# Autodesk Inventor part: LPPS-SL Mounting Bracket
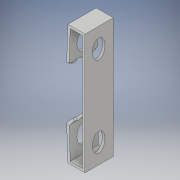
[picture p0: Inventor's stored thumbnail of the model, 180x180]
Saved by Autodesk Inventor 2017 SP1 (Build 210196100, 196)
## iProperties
Created: 2016-12
Part Number: LPPS-SL Mounting Bracket
Material: Generic
Document SubType Name: Modeling
Designer: JN
Density: 1 g/cm^3
Appearance: Default
Author: JN
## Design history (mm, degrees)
sketch "Sketch1"
  geometry: L1 (0, 0)-(0, 38.735) reference; L2 (0, 38.735)-(-5.524, 38.735); L3 (-5.524, 38.735)-(-5.905, 27.737); L4 (0, 0)-(-5.524, 0) reference; L5 (-5.524, 0)-(-5.905, 10.998); L6 (-5.905, 27.737)-(-5.568, 27.102); L7 (-5.905, 10.998)-(-5.568, 11.633); L8 (-4.92, 27.588)-(-5.098, 27.923); L9 (-5.098, 27.923)-(-4.752, 37.935); L10 (-4.752, 37.935)-(-0.8, 37.935); L11 (-0.8, 37.935)-(-0.8, 0.8); L12 (-0.8, 0.8)-(-4.752, 0.8); L13 (-4.752, 0.8)-(-5.098, 10.812); L14 (-5.098, 10.812)-(-4.861, 11.257); L15 (-5.568, 27.102)-(-4.92, 27.588); L16 (-5.568, 11.633)-(-4.861, 11.257)
  constraints: 32 end point, 3 perpendicular, 2 horizontal, 2 vertical, 6 other
  dimensions: "d6" = 38.735 distance of L1.start L1.end; "d7" = 5.5245 distance of L1.end L2.end; "d8" = 11.6332 distance of L2.end L6.end; "d9" = 5.5245 distance of L1.start L4.end; "d10" = 11.6332 distance of L4.end L7.end; "d27" = 150 deg angle of L6 L3; "d28" = 0.635 vertical distance of L3.end L6.end; "d29" = 150 deg angle of L5 L7; "d30" = 0.635 vertical distance of L5.end L7.end; "d31" = 0.8001 distance between parallel lines of L3 L9; "d64" = 5.9055 distance from line of L1 L3.end; "d65" = 5.9055 distance from line of L1 L5.end
extrude "Extrusion1" new body sketch "Sketch1" distance "d20" = 9.144; taper "d21" = 0 deg
sketch "Sketch3"
  geometry: L1 (9.144, 10.25)-(9.144, 0.719) reference; L2 (0, 10.25)-(0, 0.719) reference; L3 (9.144, -26.541)-(9.144, 7.655) reference; L4 (0, 0.719)-(1.524, 0); L5 (1.524, 0)-(3.052, 0.712); L6 (3.048, 0.71)-(4.572, 0); L7 (4.572, 0)-(6.092, 0.718); L8 (6.102, 0.722)-(7.62, 0); L9 (7.62, 0)-(9.144, 0.71); L10 (0, 0.719)-(0, 0); L11 (0, 0.505)-(0, 9.18) reference; L12 (9.144, 0.71)-(9.144, 0); L13 (0, -26.541)-(0, 7.655) reference; L14 (0, 0)-(1.524, 0); L15 (0, 0)-(9.144, 0) reference; L16 (1.524, 0)-(4.572, 0); L17 (4.572, 0)-(7.62, 0); L18 (7.62, 0)-(9.144, 0); L19 (0, 0.719)-(9.144, 0.719); L20 (9.144, 0.719)-(9.144, 0); L21 (9.144, 0)-(0, 0); L22 (0, 0)-(0, 0.719); L23 (1.524, 0)-(3.048, 0.71); L24 (3.048, 0.71)-(4.572, 0); L25 (4.572, 0)-(1.524, 0); L26 (4.572, 0)-(6.102, 0.722); L27 (6.102, 0.722)-(7.62, 0); L28 (7.62, 0)-(4.572, 0); L29 (0, 0.719)-(9.144, 0.719) reference; L30 (7.62, 0)-(9.144, 0.719); L31 (9.144, 0)-(9.144, 0.505) reference; L32 (9.144, 0.719)-(9.144, 0); L33 (9.144, 0)-(7.62, 0)
  constraints: 50 end point, 11 collinear, 4 parallel, 3 equal length, 1 horizontal, 1 perpendicular
  dimensions: "d37" = 9.144 distance between parallel lines of L1 L2 (derived); "d55" = 3.048 distance of L6.end L4.end
extrude "Extrusion2" cut sketch "Sketch3" stored distance "d56" = 25.4; taper "d57" = 0 deg
node "Sketch4"
workplane "Work Plane1"
mirror "Mirror1"
sketch "Sketch5" dims "d58" = 2.032, "d59" = 3.048
  geometry: L1 (0, 38.735)-(-9.144, 38.735) reference; L2 (-9.144, 38.735)-(0, 38.735); L3 (0, 0)-(-9.144, 0) reference; L4 (-9.144, 38.735)-(-9.144, 0); L5 (-9.144, 19.368)-(0, 19.368); L6 (0, 37.935)-(0, 0.8) reference; 2 further points; 2 other entities
  constraints: 6 end point, 2 midpoint, 1 collinear, 1 horizontal, 1 perpendicular, 1 symmetric about line, 4 other
  dimensions: "d60" = 6.35 distance from line of point (-4.754, 32.385) L1
extrude "Extrusion3" cut sketch "Sketch5" stored distance "d61" = 25.4; taper "d62" = 0 deg
body "Solid1"
